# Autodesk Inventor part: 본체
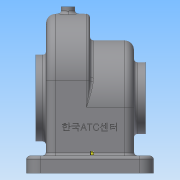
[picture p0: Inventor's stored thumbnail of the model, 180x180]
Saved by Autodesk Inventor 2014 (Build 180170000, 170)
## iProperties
Created: 2017-11
Part Number: 본체
Material: 일반
Document SubType Name: Modeling
Designer: net
Density: 1 g/cm^3
Appearance: 기본값
Author: net
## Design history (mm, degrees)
sketch "스케치1"
  geometry: L1 (-55, 75)-(55, 75); L2 (55, 75)-(55, -75); L3 (55, -75)-(-55, -75); L4 (-55, -75)-(-55, 75); 3 further points
  constraints: 8 end point, 2 midpoint, 2 parallel, 1 horizontal, 1 horizontal alignment, 1 perpendicular, 1 vertical alignment
  dimensions: "d0" = 110 distance of L1.start L1.end; "d1" = 150 distance of L3.end L1.start
extrude "돌출1" new body sketch "스케치1" distance "d2" = 15; taper "d3" = 0 deg
fillet "모깎기1" dims "d4" = 12
hole "구멍1" diameter "d7" = 5; stored, may be unused: countersink angle "d11" = 90 deg, drill point angle "d13" = 118 deg; dims "d5" = 10, "d6" = 10, "d8" = 6, "d9" = 12, "d10" = 5, "d12" = 8
hole "구멍2" diameter "d16" = 5; stored, may be unused: countersink angle "d20" = 90 deg, drill point angle "d22" = 118 deg; dims "d14" = 10, "d15" = 10, "d17" = 6, "d18" = 12, "d19" = 5, "d21" = 8
node "작업 평면1"
sketch "스케치3"
  geometry: L1 (5, 80)-(121, 80); L2 (121, 80)-(121, 15); L3 (121, 15)-(5, 15); L4 (5, 15)-(5, 80); L5 (126, 15)-(0, 15) reference; L6 (0, 15)-(0, 0) reference; L7 (126, 15)-(0, 15) reference; L8 (126, 0)-(126, 15) reference; L9 (0, 0)-(126, 0) reference; 4 further points
  constraints: 8 end point, 3 midpoint, 2 parallel, 1 collinear, 1 horizontal, 1 horizontal alignment, 1 perpendicular, 1 vertical alignment, 2 other
  dimensions: "d24" = 116 distance between parallel lines of L2 L4; "d25" = 80 distance between parallel lines of L9 L1
extrude "돌출2" join sketch "스케치3" distance "d26" = 38; taper "d27" = 0 deg
node "작업 평면2"
sketch "스케치4"
  geometry: L1 (15, 121)-(15, 5) reference; L2 (0, 126)-(0, 0) reference; L3 (57, 121)-(15, 121); L4 (15, 121)-(15, 5); L5 (15, 5)-(57, 5); L6 (57, 5)-(57, 121); A1 r 58 centre (57, 63) between (57, 5) and (57, 121); 2 further points
  constraints: 8 end point, 2 midpoint, 2 parallel, 2 point on circle, 1 centre point, 1 collinear, 1 horizontal, 1 horizontal alignment, 1 perpendicular
  dimensions: "d30" = 58 radius of A1; "d31" = 57 distance between parallel lines of L2 L6
extrude "돌출3" join sketch "스케치4" distance "d32" = 38; taper "d33" = 0 deg
sketch "스케치5" dims "d34" = 106
  geometry: L1 (5, 15)-(5, 57) reference; L2 (121, 57)-(121, 15) reference; L3 (10, 57)-(116, 57); L4 (116, 57)-(116, 0); L5 (116, 0)-(10, 0); L6 (10, 0)-(10, 57); L7 (0, 0)-(126, 0) reference; A1 r 58 centre (63, 57) between (121, 57) and (5, 57) reference; 2 further points
  constraints: 8 end point, 2 parallel, 1 coincident, 1 collinear, 1 horizontal, 1 horizontal alignment, 1 midpoint, 1 perpendicular, 2 other
extrude "돌출4" cut sketch "스케치5" distance "d35" = 33; taper "d36" = 0 deg
sketch "스케치6" dims "d37" = 106
  geometry: L1 (126, 0)-(0, 0) reference; L2 (5, 80)-(5, 15) reference; L3 (121, 15)-(5, 15) reference; L4 (121, 15)-(121, 80) reference; L5 (5, 80)-(5, 15) reference; L6 (10, 80)-(116, 80); L7 (116, 80)-(116, 0); L8 (116, 0)-(10, 0); L9 (10, 0)-(10, 80); A1 r 58 centre (63, 80) between (121, 80) and (5, 80) reference; A2 r 58 centre (63, 80) between (121, 80) and (5, 80) reference; 3 further points
  constraints: 8 end point, 2 midpoint, 2 parallel, 1 coincident, 1 collinear, 1 horizontal, 1 horizontal alignment, 1 perpendicular, 1 vertical alignment, 2 other
extrude "돌출5" cut sketch "스케치6" distance "d38" = 33; taper "d39" = 0 deg
sketch "스케치7"
  geometry: L1 (121, 80)-(121, 57); L2 (5, 57)-(5, 80); L3 (9.755, 80)-(10, 80); L4 (116, 80)-(116.245, 80); L5 (5, 57)-(10, 57); L6 (116, 57)-(121, 57); A1 r 58 centre (63, 80) between (121, 80) and (5, 80) reference; A2 r 53 centre (63, 80) between (116, 80) and (10, 80) reference; A3 r 58 centre (63, 80) between (121, 80) and (5, 80); A4 r 58 centre (63, 57) between (121, 57) and (5, 57) reference; A5 r 53 centre (63, 57) between (116, 57) and (10, 57) reference; A6 r 53 centre (63, 57) between (116, 57) and (10, 57); 1 further point
  constraints: 12 end point, 10 point on circle, 4 perpendicular, 2 centre point, 2 coincident, 2 concentric, 2 horizontal, 1 parallel, 1 tangent
  dimensions: "d96" = 23 distance between parallel lines of L6 L4; "d97" = 23 distance between parallel lines of L6 L3
extrude "돌출6" join sketch "스케치7" distance "d43" = 5; taper "d44" = 0 deg
sketch "스케치8"
  geometry: L1 (126, 0)-(0, 0) reference; C1 r 37.5 at (63, 65); C2 r 16 at (63, 65); 2 further points
  constraints: 2 centre point, 1 coincident, 1 midpoint, 1 vertical alignment
  dimensions: "d45" = 65 distance from line of L1 C1.centre; "d46" = 75 diameter of C1; "d47" = 32 diameter of C2
extrude "돌출7" join sketch "스케치8" distance "d48" = 9; taper "d49" = 0 deg
extrude "돌출8" cut sketch "스케치8" stored distance "d50" = 9; taper "d51" = 0 deg
sketch "스케치9" dims "d52" = 58
  geometry: C1 r 16 at (0, 0) reference; C2 r 37.5 at (0, 0) reference; 3 further points
  constraints: 2 vertical alignment, 1 coincident, 2 other
hole "구멍3" sketch "스케치9" at (0, 29) diameter "d53" = 2.459; stored, may be unused: countersink angle "d57" = 90 deg, drill point angle "d59" = 118 deg; dims "d54" = 6, "d55" = 12, "d56" = 5, "d58" = 8
sketch "스케치10" dims "d64" = 52
  geometry: C1 r 16 at (-63, 65) reference; C2 r 31 at (-63, 65); 3 further points
  constraints: 2 coincident, 2 vertical alignment, 1 centre point, 2 other
  dimensions: "d63" = 62 diameter of C2
extrude "돌출9" join sketch "스케치10" distance "d65" = 10; taper "d66" = 0 deg
sketch "스케치11" dims "d67" = 52
  geometry: C1 r 16 at (0, 0) reference; C2 r 31 at (0, 0) reference; 3 further points
  constraints: 2 vertical alignment, 1 coincident, 2 other
hole "구멍4" sketch "스케치11" at (0, 26) diameter "d68" = 2.459; stored, may be unused: countersink angle "d72" = 90 deg, drill point angle "d74" = 118 deg; dims "d69" = 6, "d70" = 12, "d71" = 5, "d73" = 8
node "작업 평면3"
sketch "스케치12"
  geometry: L1 (38, -58)-(38, 58) reference; L2 (0, 58)-(0, -58) reference; C1 r 6 at (19, 0); 3 further points
  constraints: 2 midpoint, 1 centre point, 1 coincident, 1 horizontal alignment
  dimensions: "d79" = 19 distance from line of L1 C1.centre; "d80" = 12 diameter of C1
extrude "돌출10" join sketch "스케치12" stored distance "d81" = 10; taper "d82" = 0 deg
hole "구멍5" diameter "d85" = 4.459; stored, may be unused: countersink angle "d89" = 90 deg, drill point angle "d91" = 118 deg; dims "d86" = 6, "d87" = 12, "d88" = 5, "d90" = 44, "d110" = 10, "d111" = 10
chamfer "모따기1" distance "d92" = 1; stored, may be unused: second distance "d93" = 2, angle "d94" = 45 deg
fillet "모깎기2" dims "d95" = 8
extrude "돌출11" join sketch "스케치7" distance "d98" = 5; taper "d99" = 0 deg
fillet "모깎기3" dims "d100" = 3
fillet "모깎기4" dims "d101" = 3
fillet "모깎기5" dims "d102" = 3
fillet "모깎기6" dims "d103" = 3
sketch "스케치13"
  geometry: L1 (-8, 62)-(-8, 0) reference; L2 (73, -18)-(-13, -18) reference; 2 further points
  constraints: 1 other
  dimensions: "d104" = 38 distance from line of L1 point (30, 22); "d105" = 40 distance from line of L2 point (30, 22)
feature "엠보싱1" sketch "스케치13" dims "d106" = 0.5, "d107" = 0
node "솔리드1"
mirror "대칭1"
pattern_circular "원형 패턴1" dims angle "d61" = 360 deg
pattern_circular "원형 패턴2" dims angle "d76" = 360 deg
node "투영된 루프1"
node "투영된 루프2"
other parameters: "d23" = -55, "d28" = -55, "d29" = 116, "d78" = -144
